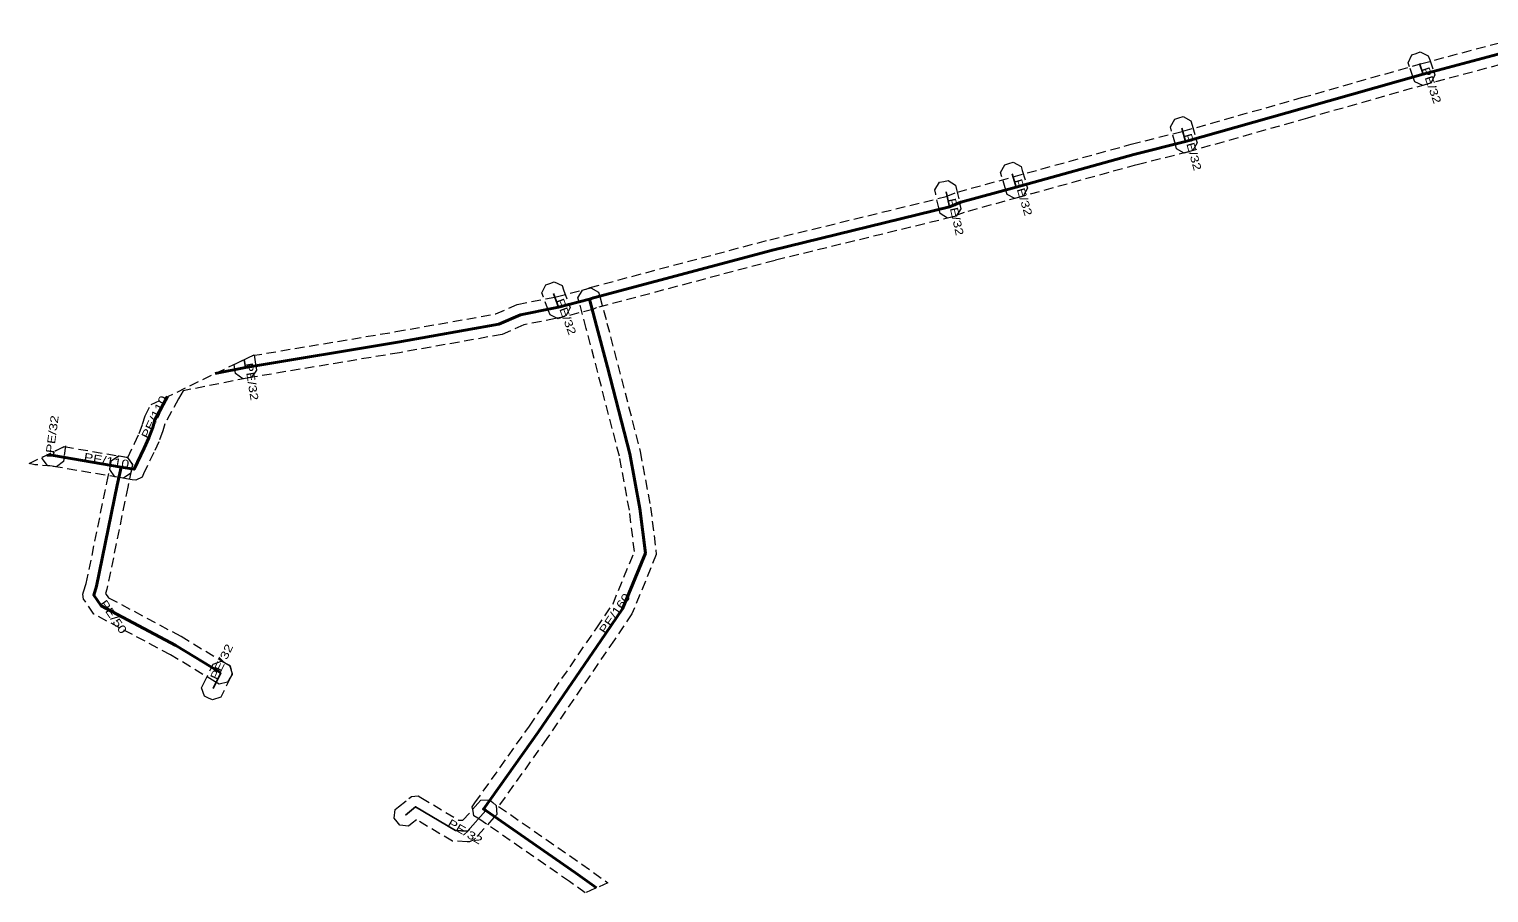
# Model space of a CAD drawing. Extents: x -772780 to -772236, y -1033108 to -1032817.
# Drawn here: x -772779.7 to -772643, y -1033107.6 to -1033026.7 of the extents above; entities that cross this region are included whole.
import ezdxf

# ---------------------------------------------------------------- set-up
doc = ezdxf.new("R2010")
doc.units = 0
doc.header["$LTSCALE"] = 0.3
doc.linetypes.add('MEDIUM_DASHED', pattern=[4.5, 3, -1.5])
doc.layers.add('1', color=7, linetype='MEDIUM_DASHED', lineweight=13)
doc.layers.add('24', color=7, linetype='Continuous', lineweight=25)
doc.layers.add('30', color=7, linetype='Continuous')

msp = doc.modelspace()

# ---------------------------------------------------------------- linework, layer by layer
at = {"layer": '1'}
for points in [[(-772768.308, -1033061.865), (-772758.823, -1033057.276), (-772745.365, -1033055.029), (-772736.012, -1033053.364), (-772733.993, -1033052.476), (-772730.805, -1033051.846), (-772730.354, -1033051.755), (-772727.537, -1033051.029), (-772727.315, -1033050.943), (-772727.18, -1033050.891), (-772710.339, -1033046.405), (-772693.803, -1033042.36), (-772692.755, -1033041.942), (-772687.527, -1033040.511), (-772676.488, -1033037.46), (-772671.629, -1033036.24), (-772660.513, -1033033.085), (-772649.366, -1033029.916), (-772637.216, -1033026.666)], [(-772636.672, -1033028.59), (-772648.834, -1033031.844), (-772659.967, -1033035.009), (-772671.113, -1033038.172), (-772675.978, -1033039.394), (-772686.997, -1033042.439), (-772692.119, -1033043.842), (-772693.191, -1033044.27), (-772709.843, -1033048.343), (-772726.558, -1033052.795), (-772726.593, -1033052.809), (-772726.927, -1033052.937), (-772729.906, -1033053.705), (-772730.413, -1033053.808), (-772733.389, -1033054.396), (-772735.426, -1033055.292), (-772745.025, -1033056.999), (-772759.295, -1033059.382), (-772765.302, -1033060.571), (-772765.751, -1033061.343), (-772767.015, -1033063.677), (-772767.204, -1033064.321), (-772767.581, -1033065.361), (-772768.059, -1033066.369), (-772769.003, -1033068.356), (-772769.146, -1033068.658), (-772769.74, -1033068.968)], [(-772769.74, -1033068.968), (-772770.07, -1033068.913), (-772771.282, -1033068.711), (-772771.691, -1033068.643), (-772772.172, -1033067.969), (-772772.104, -1033067.561), (-772772.036, -1033067.152), (-772771.362, -1033066.671), (-772770.954, -1033066.739), (-772770.486, -1033066.817), (-772769.865, -1033065.511), (-772769.429, -1033064.591), (-772769.106, -1033063.699), (-772768.875, -1033062.911), (-772768.308, -1033061.865)]]:
    msp.add_lwpolyline(points, dxfattribs=at)
for points in [[(-772649.907, -1033031.601), (-772650.044, -1033031.21), (-772650.394, -1033030.21), (-772650.531, -1033029.819), (-772650.171, -1033029.073), (-772649.78, -1033028.936), (-772649.389, -1033028.799), (-772648.643, -1033029.159), (-772648.506, -1033029.55), (-772648.156, -1033030.55), (-772648.019, -1033030.941), (-772648.379, -1033031.687), (-772648.77, -1033031.824), (-772649.161, -1033031.961)], [(-772672.222, -1033037.875), (-772672.334, -1033037.477), (-772672.689, -1033036.215), (-772672.801, -1033035.816), (-772672.395, -1033035.093), (-772671.997, -1033034.981), (-772671.598, -1033034.869), (-772670.875, -1033035.275), (-772670.763, -1033035.673), (-772670.408, -1033036.935), (-772670.296, -1033037.334), (-772670.702, -1033038.057), (-772671.1, -1033038.169), (-772671.499, -1033038.281)], [(-772688.102, -1033042.157), (-772688.22, -1033041.76), (-772688.595, -1033040.501), (-772688.713, -1033040.104), (-772688.319, -1033039.376), (-772687.922, -1033039.258), (-772687.525, -1033039.14), (-772686.797, -1033039.534), (-772686.679, -1033039.931), (-772686.304, -1033041.19), (-772686.186, -1033041.587), (-772686.58, -1033042.315), (-772686.977, -1033042.433), (-772687.374, -1033042.551)], [(-772694.383, -1033043.936), (-772694.473, -1033043.532), (-772694.785, -1033042.13), (-772694.875, -1033041.726), (-772694.43, -1033041.027), (-772694.026, -1033040.937), (-772693.622, -1033040.847), (-772692.923, -1033041.292), (-772692.833, -1033041.696), (-772692.521, -1033043.098), (-772692.431, -1033043.502), (-772692.876, -1033044.201), (-772693.28, -1033044.291), (-772693.684, -1033044.381)], [(-772730.928, -1033053.461), (-772731.07, -1033053.072), (-772731.54, -1033051.782), (-772731.682, -1033051.393), (-772731.331, -1033050.642), (-772730.942, -1033050.5), (-772730.553, -1033050.358), (-772729.802, -1033050.709), (-772729.66, -1033051.098), (-772729.19, -1033052.388), (-772729.048, -1033052.777), (-772729.399, -1033053.528), (-772729.788, -1033053.67), (-772730.177, -1033053.812)], [(-772725.497, -1033106.706), (-772727.621, -1033107.647), (-772729.105, -1033106.586), (-772737.495, -1033100.772), (-772737.594, -1033100.711), (-772737.693, -1033100.649), (-772738.059, -1033100.42), (-772738.144, -1033099.997), (-772738.228, -1033099.573), (-772737.978, -1033099.221), (-772732.856, -1033092.022), (-772726.548, -1033082.797), (-772725.026, -1033080.542), (-772723.017, -1033075.648), (-772723.489, -1033071.776), (-772724.427, -1033066.709), (-772727.525, -1033054.729), (-772728.197, -1033052.244), (-772728.306, -1033051.844), (-772727.893, -1033051.126), (-772727.493, -1033051.018), (-772727.093, -1033050.909), (-772726.375, -1033051.322), (-772726.267, -1033051.722), (-772725.591, -1033054.217), (-772722.473, -1033066.277), (-772721.511, -1033071.472), (-772720.969, -1033075.924), (-772723.254, -1033081.492), (-772724.894, -1033083.921), (-772731.216, -1033093.166), (-772735.754, -1033099.545), (-772727.953, -1033104.95)], [(-772760.535, -1033058.104), (-772758.656, -1033057.195), (-772758.487, -1033058.238), (-772758.421, -1033058.647), (-772758.905, -1033059.319), (-772759.314, -1033059.385), (-772759.723, -1033059.451), (-772760.395, -1033058.967), (-772760.461, -1033058.558)], [(-772779.211, -1033067.508), (-772779.728, -1033067.39), (-772776.453, -1033065.806), (-772770.951, -1033066.739), (-772770.543, -1033066.808), (-772770.063, -1033067.484), (-772770.132, -1033067.892), (-772770.201, -1033068.3), (-772770.877, -1033068.78), (-772771.285, -1033068.711), (-772777.582, -1033067.643)], [(-772778.484, -1033066.789), (-772776.326, -1033065.745), (-772776.466, -1033066.783), (-772776.521, -1033067.193), (-772777.18, -1033067.696), (-772777.59, -1033067.641), (-772778, -1033067.586), (-772778.503, -1033066.927)], [(-772770.053, -1033067.53), (-772770.14, -1033067.935), (-772770.501, -1033069.612), (-772772.438, -1033079.159), (-772772.57, -1033079.567), (-772772.286, -1033079.984), (-772765.498, -1033083.592), (-772761.261, -1033086.155), (-772760.907, -1033086.37), (-772760.709, -1033087.174), (-772760.923, -1033087.529), (-772761.138, -1033087.883), (-772761.942, -1033088.081), (-772762.297, -1033087.867), (-772766.486, -1033085.332), (-772773.66, -1033081.518), (-772774.498, -1033080.289), (-772774.629, -1033080.098), (-772774.695, -1033079.639), (-772774.624, -1033079.419), (-772774.376, -1033078.651), (-772772.459, -1033069.202), (-772772.096, -1033067.515), (-772772.009, -1033067.11), (-772771.313, -1033066.66), (-772770.908, -1033066.747), (-772770.503, -1033066.834)], [(-772760.698, -1033087.073), (-772760.879, -1033087.446), (-772761.591, -1033088.919), (-772761.771, -1033089.292), (-772762.553, -1033089.565), (-772762.926, -1033089.384), (-772763.299, -1033089.204), (-772763.572, -1033088.422), (-772763.391, -1033088.049), (-772762.679, -1033086.576), (-772762.499, -1033086.203), (-772761.717, -1033085.93), (-772761.344, -1033086.111), (-772760.971, -1033086.291)], [(-772745.434, -1033099.835), (-772745.112, -1033099.574), (-772744.158, -1033098.802), (-772743.914, -1033098.604), (-772743.287, -1033098.559), (-772743.017, -1033098.72), (-772739.494, -1033100.82), (-772739.085, -1033100.835), (-772737.694, -1033099.271), (-772737.419, -1033098.961), (-772736.592, -1033098.913), (-772736.283, -1033099.188), (-772735.973, -1033099.463), (-772735.925, -1033100.29), (-772736.2, -1033100.599), (-772737.904, -1033102.516), (-772738.053, -1033102.684), (-772738.464, -1033102.86), (-772738.688, -1033102.851), (-772740.078, -1033102.8), (-772743.442, -1033100.795), (-772743.854, -1033101.128), (-772744.176, -1033101.389), (-772744.999, -1033101.302), (-772745.26, -1033100.98), (-772745.521, -1033100.658)]]:
    msp.add_lwpolyline(points, close=True, dxfattribs=at)
at = {"layer": '24'}
for p, q in [((-772649.1, -1033030.88), (-772649.45, -1033029.88)), ((-772671.371, -1033037.206), (-772671.726, -1033035.944)), ((-772687.262, -1033041.475), (-772687.637, -1033040.216)), ((-772693.497, -1033043.315), (-772693.809, -1033041.913)), ((-772730.13, -1033052.73), (-772730.6, -1033051.44)), ((-772759.474, -1033058.398), (-772759.595, -1033057.649)), ((-772777.457, -1033066.65), (-772777.405, -1033066.267)), ((-772761.779, -1033087.011), (-772762.491, -1033088.484))]:
    msp.add_line(p, q, dxfattribs=at)
at = {"layer": '24', "lineweight": 40}
for points in [[(-772636.944, -1033027.628), (-772649.1, -1033030.88), (-772660.24, -1033034.047), (-772671.371, -1033037.206), (-772676.233, -1033038.427), (-772687.262, -1033041.475), (-772692.437, -1033042.892), (-772693.497, -1033043.315), (-772710.091, -1033047.374), (-772726.869, -1033051.843), (-772726.954, -1033051.876), (-772727.232, -1033051.983), (-772730.13, -1033052.73), (-772730.609, -1033052.827), (-772733.691, -1033053.436), (-772735.719, -1033054.328), (-772745.195, -1033056.014), (-772759.474, -1033058.398), (-772762.298, -1033058.957)], [(-772727.232, -1033051.983), (-772726.558, -1033054.473), (-772725.553, -1033058.363), (-772723.45, -1033066.493), (-772722.5, -1033071.624), (-772721.993, -1033075.786), (-772724.14, -1033081.017), (-772725.72, -1033083.358), (-772732.036, -1033092.594), (-772737.163, -1033099.801), (-772737.067, -1033099.861), (-772736.947, -1033099.935), (-772728.529, -1033105.768), (-772726.559, -1033107.177)], [(-772766.767, -1033061.119), (-772767.945, -1033063.294), (-772768.155, -1033064.01), (-772768.505, -1033064.976), (-772768.962, -1033065.94), (-772769.906, -1033067.927), (-772771.118, -1033067.725)], [(-772771.118, -1033067.725), (-772777.457, -1033066.65), (-772778.089, -1033066.597)], [(-772771.118, -1033067.725), (-772771.48, -1033069.407), (-772773.406, -1033078.904), (-772773.672, -1033079.726), (-772772.973, -1033080.751), (-772765.991, -1033084.461), (-772761.779, -1033087.011)]]:
    msp.add_lwpolyline(points, dxfattribs=at)
at = {"layer": '24'}
msp.add_lwpolyline([(-772744.483, -1033100.351), (-772743.529, -1033099.579), (-772739.786, -1033101.81), (-772738.651, -1033101.852), (-772736.947, -1033099.935)], dxfattribs=at)

# ---------------------------------------------------------------- texts
at = {"layer": '30', "width": 1.3}
for s, rotation, p in [('PE/32', 289.29, (-772649.275, -1033030.38)), ('PE/32', 285.711, (-772671.548, -1033036.575)), ('PE/32', 286.586, (-772687.449, -1033040.845)), ('PE/32', 282.546, (-772693.653, -1033042.614)), ('PE/32', 290.019, (-772730.365, -1033052.085)), ('PE/32', 279.21, (-772759.535, -1033058.023)), ('PE/110', 64.636, (-772768.58, -1033065.133)), ('PE/32', 82.335, (-772777.431, -1033066.458)), ('PE/110', 350.375, (-772774.649, -1033067.126)), ('PE/50', 304.292, (-772773.138, -1033080.509)), ('PE/160', 55.634, (-772725.767, -1033083.426)), ('PE/32', 64.202, (-772762.135, -1033087.747)), ('PE/32', 329.203, (-772740.595, -1033101.327))]:
    msp.add_text(s, height=0.75, rotation=rotation, dxfattribs=at).set_placement(p)

doc.saveas('drawing.dxf')
